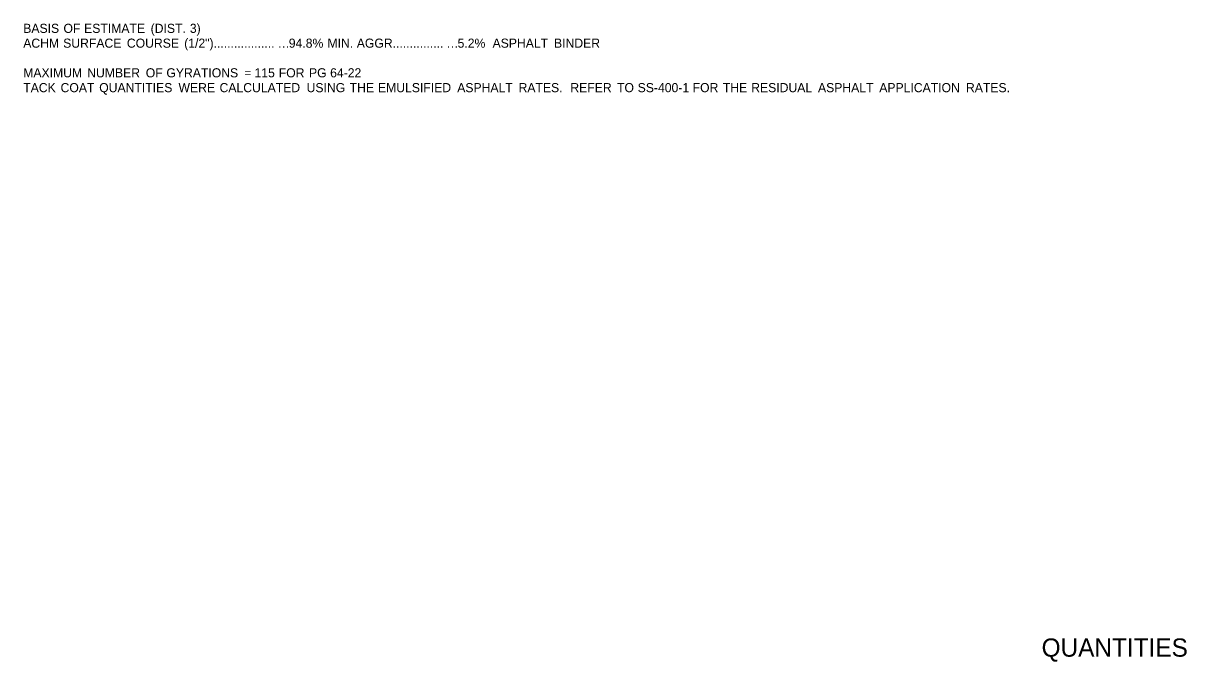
# Model space of a CAD drawing. Extents: x 544250 to 1930787, y -1948365 to 596640.
# Drawn here: x 558323 to 559089, y -1947044 to -1946624 of the extents above; entities that cross this region are included whole.
import ezdxf

# ---------------------------------------------------------------- set-up
doc = ezdxf.new("R2010")
doc.units = 0
doc.layers.add('Default', color=7, linetype='Continuous')
doc.layers.add('R_Border', color=7, linetype='Continuous')

msp = doc.modelspace()

# ---------------------------------------------------------------- texts
at = {"layer": 'Default'}
for s, p in [('BASIS', (558322.6, -1946630.66)), (' OF', (558346.86, -1946630.66)), (' ESTIMATE', (558360.45, -1946630.66)), (' (DIST.', (558404.26, -1946630.66)), (' 3)', (558430.07, -1946630.66)), ('ACHM', (558322.6, -1946640.41)), (' SURFACE', (558346.66, -1946640.41)), (' COURSE', (558388.6, -1946640.41)), (' (1/2")..................', (558426.36, -1946640.41)), ('94.8%', (558497.45, -1946640.41)), (' MIN.', (558520.7, -1946640.41)), (' AGGR...............', (558539.98, -1946640.41)), ('5.2%', (558608.59, -1946640.41)), ('  ASPHALT', (558627.17, -1946640.41)), (' BINDER', (558669.86, -1946640.41)), ('…', (558490.06, -1946640.41)), ('…', (558601.19, -1946640.41)), ('MAXIMUM', (558322.6, -1946659.91)), (' NUMBER', (558362.49, -1946659.91)), (' OF', (558401.04, -1946659.91)), (' GYRATIONS', (558414.63, -1946659.91)), (' =', (558465.9, -1946659.91)), (' 115', (558472.65, -1946659.91)), (' FOR', (558488.62, -1946659.91)), (' PG', (558508.54, -1946659.91)), (' 64-22', (558522.45, -1946659.91)), ('TACK', (558322.6, -1946669.66)), (' COAT', (558344.95, -1946669.66)), (' QUANTITIES', (558370.4, -1946669.66)), (' WERE', (558422.6, -1946669.66)), (' CALCULATED', (558449.63, -1946669.66)), (' USING', (558506.95, -1946669.66)), (' THE', (558535.3, -1946669.66)), (' EMULSIFIED', (558553.95, -1946669.66)), (' ASPHALT', (558606.14, -1946669.66)), (' RATES.', (558646.51, -1946669.66)), ('  REFER', (558678.39, -1946669.66)), (' TO', (558711.35, -1946669.66)), (' SS-400-1', (558724.94, -1946669.66)), (' FOR', (558761.13, -1946669.66)), (' THE', (558781.05, -1946669.66)), (' RESIDUAL', (558799.7, -1946669.66)), (' ASPHALT', (558843.66, -1946669.66)), (' APPLICATION', (558884.02, -1946669.66)), (' RATES.', (558941.11, -1946669.66))]:
    msp.add_text(s, height=6, dxfattribs=at).set_placement(p)
at = {"layer": 'R_Border'}
msp.add_text('QUANTITIES', height=12, rotation=360, dxfattribs=at).set_placement((558993.14, -1947040.95))

doc.saveas('drawing.dxf')
